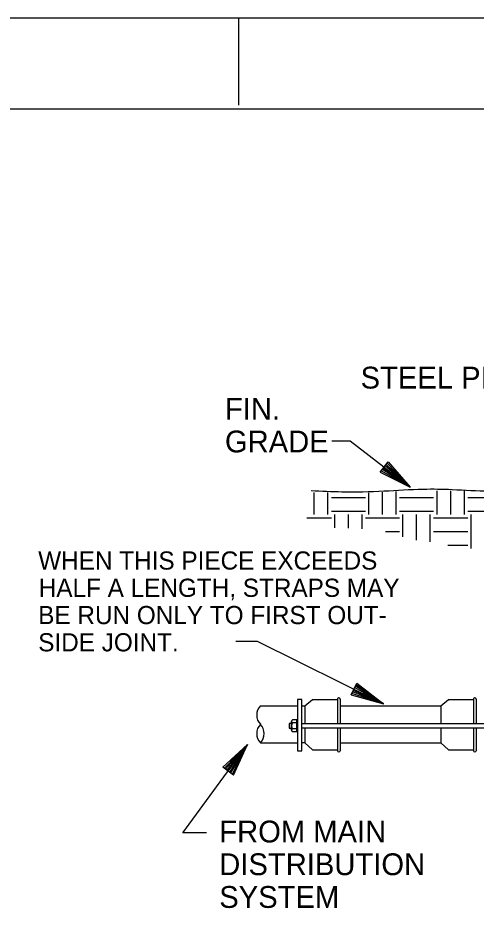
# Model space of a CAD drawing. Extents: x 9999.96 to 10005.26, y 9999.88 to 10002.38.
# Drawn here: x 10001.0957 to 10001.3058, y 10001.9764 to 10002.3845 of the extents above; entities that cross this region are included whole.
import ezdxf

# ---------------------------------------------------------------- set-up
doc = ezdxf.new("R2010")
doc.units = 0
doc.layers.add('Level 1', color=7, linetype='Continuous')
doc.layers.add('Level 2', color=7, linetype='Continuous')

msp = doc.modelspace()

# ---------------------------------------------------------------- linework, layer by layer
at = {"layer": 'Level 1'}
for p, q in [((9999.96033, 10002.38453), (10003.46033, 10002.38453)), ((10001.19683, 10002.38453), (10001.19683, 10002.3445)), ((10000.127, 10002.34286), (10003.41867, 10002.34286))]:
    msp.add_line(p, q, dxfattribs=at)
at = {"layer": 'Level 2'}
for p, q in [((10001.26183, 10002.17618), (10001.26551, 10002.18096)), ((10001.2756, 10002.1694), (10001.26322, 10002.17799)), ((10001.26364, 10002.17855), (10001.2756, 10002.1694)), ((10001.2756, 10002.1694), (10001.2641, 10002.17915)), ((10001.2756, 10002.1694), (10001.26455, 10002.17974)), ((10001.2756, 10002.1694), (10001.265, 10002.18031)), ((10001.26551, 10002.18096), (10001.2756, 10002.1694)), ((10001.26183, 10002.17618), (10001.2756, 10002.1694)), ((10001.2756, 10002.1694), (10001.2623, 10002.17679)), ((10001.2756, 10002.1694), (10001.26279, 10002.17747)), ((10001.2316, 10002.15684), (10001.2316, 10002.16698)), ((10001.23785, 10002.15684), (10001.23785, 10002.16698)), ((10001.2566, 10002.15684), (10001.2566, 10002.16681)), ((10001.26285, 10002.15684), (10001.26285, 10002.16714)), ((10001.2691, 10002.15684), (10001.2691, 10002.16745)), ((10001.28785, 10002.15684), (10001.28785, 10002.16775)), ((10001.2941, 10002.15684), (10001.2941, 10002.16777)), ((10001.30035, 10002.15684), (10001.30035, 10002.16788)), ((10001.23942, 10002.16466), (10001.25504, 10002.16466)), ((10001.27067, 10002.16466), (10001.28629, 10002.16466)), ((10001.30192, 10002.16466), (10001.31754, 10002.16466)), ((10001.23942, 10002.15841), (10001.25504, 10002.15841)), ((10001.27067, 10002.15841), (10001.28629, 10002.15841)), ((10001.30192, 10002.15841), (10001.31754, 10002.15841)), ((10001.22814, 10002.15528), (10001.23942, 10002.15528)), ((10001.24098, 10002.15072), (10001.24098, 10002.15684)), ((10001.24723, 10002.15053), (10001.24723, 10002.15684)), ((10001.25348, 10002.15033), (10001.25348, 10002.15684)), ((10001.25504, 10002.15528), (10001.27067, 10002.15528)), ((10001.27223, 10002.14657), (10001.27223, 10002.15684)), ((10001.27848, 10002.1451), (10001.27848, 10002.15684)), ((10001.28473, 10002.14425), (10001.28473, 10002.15684)), ((10001.28629, 10002.15528), (10001.30192, 10002.15528)), ((10001.30348, 10002.14122), (10001.30348, 10002.15684)), ((10001.26425, 10002.14903), (10001.27067, 10002.14903)), ((10001.28629, 10002.14903), (10001.30192, 10002.14903)), ((10001.29275, 10002.14278), (10001.30192, 10002.14278)), ((10001.24843, 10002.07413), (10001.25111, 10002.07952)), ((10001.26325, 10002.07013), (10001.24944, 10002.07617)), ((10001.24974, 10002.0768), (10001.26325, 10002.07013)), ((10001.26325, 10002.07013), (10001.25008, 10002.07747)), ((10001.26325, 10002.07013), (10001.25041, 10002.07815)), ((10001.26325, 10002.07013), (10001.25074, 10002.07878)), ((10001.25111, 10002.07952), (10001.26325, 10002.07013)), ((10001.23077, 10002.07194), (10001.22718, 10002.06903)), ((10001.24225, 10002.07194), (10001.23077, 10002.07194)), ((10001.24225, 10002.07217), (10001.24225, 10002.06098)), ((10001.24343, 10002.07217), (10001.24343, 10002.06098)), ((10001.24843, 10002.07413), (10001.26325, 10002.07013)), ((10001.26325, 10002.07013), (10001.24877, 10002.07481)), ((10001.26325, 10002.07013), (10001.24913, 10002.07557)), ((10001.2931, 10002.07194), (10001.28951, 10002.06903)), ((10001.30458, 10002.07194), (10001.2931, 10002.07194)), ((10001.30458, 10002.07217), (10001.30458, 10002.06106)), ((10001.30576, 10002.07217), (10001.30576, 10002.06106)), ((10001.22394, 10002.06903), (10001.20691, 10002.06903)), ((10001.22718, 10002.06903), (10001.22583, 10002.06903)), ((10001.22718, 10002.06903), (10001.22718, 10002.06105)), ((10001.28954, 10002.06903), (10001.24347, 10002.06903)), ((10001.28951, 10002.06903), (10001.28951, 10002.06105)), ((10001.2212, 10002.05792), (10001.2212, 10002.06202)), ((10001.22353, 10002.06134), (10001.22163, 10002.06134)), ((10001.22353, 10002.06271), (10001.22164, 10002.06271)), ((10001.22353, 10002.05723), (10001.22353, 10002.06271)), ((10001.22582, 10002.06106), (10001.39957, 10002.06106)), ((10001.22353, 10002.05859), (10001.22163, 10002.05859)), ((10001.22353, 10002.05723), (10001.22163, 10002.05723)), ((10001.39957, 10002.05897), (10001.22593, 10002.05897)), ((10001.22718, 10002.05897), (10001.22718, 10002.05216)), ((10001.24225, 10002.05905), (10001.24225, 10002.04857)), ((10001.24343, 10002.05905), (10001.24343, 10002.04857)), ((10001.28951, 10002.05897), (10001.28951, 10002.05216)), ((10001.30458, 10002.05897), (10001.30458, 10002.04857)), ((10001.30576, 10002.05897), (10001.30576, 10002.04857)), ((10001.18971, 10002.041), (10001.20103, 10002.05135)), ((10001.20103, 10002.05135), (10001.19036, 10002.04051)), ((10001.20103, 10002.05135), (10001.19094, 10002.04007)), ((10001.20103, 10002.05135), (10001.19154, 10002.03964)), ((10001.19215, 10002.03919), (10001.20103, 10002.05135)), ((10001.20103, 10002.05135), (10001.19272, 10002.03878)), ((10001.20103, 10002.05135), (10001.19325, 10002.03836)), ((10001.20103, 10002.05135), (10001.19395, 10002.03789)), ((10001.19456, 10002.03743), (10001.20103, 10002.05135)), ((10001.20691, 10002.05222), (10001.22394, 10002.05222)), ((10001.22718, 10002.05221), (10001.22583, 10002.05221)), ((10001.22718, 10002.05221), (10001.23081, 10002.04894)), ((10001.24349, 10002.05222), (10001.28954, 10002.05222)), ((10001.28951, 10002.05221), (10001.29315, 10002.04894)), ((10001.23081, 10002.04894), (10001.24225, 10002.04894)), ((10001.29315, 10002.04894), (10001.30458, 10002.04894)), ((10001.19456, 10002.03743), (10001.18971, 10002.041))]:
    msp.add_line(p, q, dxfattribs=at)
for points in [[(10001.23955, 10002.19063), (10001.24795, 10002.19063), (10001.2756, 10002.1694)], [(10001.19559, 10002.09877), (10001.20547, 10002.09877), (10001.26325, 10002.07013)], [(10001.22119, 10002.0611), (10001.22004, 10002.0611), (10001.22004, 10002.05884), (10001.22119, 10002.05884)], [(10001.18226, 10002.01086), (10001.1714, 10002.01086), (10001.20103, 10002.05135)]]:
    msp.add_lwpolyline(points, dxfattribs=at)
msp.add_lwpolyline([(10001.22394, 10002.07211), (10001.22394, 10002.04856), (10001.22582, 10002.04856), (10001.22582, 10002.07211)], close=True, dxfattribs=at)
for centre, radius, start, end in [((10001.24284, 10002.07217), 0.000589, 0, 180), ((10001.30517, 10002.07217), 0.000589, 0, 180), ((10001.21127, 10002.06488), 0.00607, 135.9788, 224.0225), ((10001.21127, 10002.05644), 0.00607, 135.9775, 224.0212), ((10001.20254, 10002.05644), 0.00607, 315.9788, 44.0225), ((10001.22198, 10002.06202), 0.000766, 116.7827, 241.8391), ((10001.22374, 10002.05997), 0.00253, 147.0062, 212.943), ((10001.22197, 10002.05791), 0.000766, 117.8877, 242.0342), ((10001.24284, 10002.04857), 0.000589, 180, 0), ((10001.30517, 10002.04857), 0.000589, 180, 0)]:
    msp.add_arc(centre, radius, start, end, dxfattribs=at)
msp.add_spline([(10001.32029, 10002.16835), (10001.31184, 10002.16767), (10001.29476, 10002.16818), (10001.28147, 10002.16835), (10001.26352, 10002.16749), (10001.2442, 10002.16715), (10001.23022, 10002.16767)], degree=3, dxfattribs=at)

# ---------------------------------------------------------------- texts
for s, height, p in [('STEEL PIPE', 0.01, (10001.2528, 10002.21458)), ('FIN. ', 0.01, (10001.19063, 10002.20032)), ('GRADE', 0.01, (10001.19063, 10002.18532)), ('WHEN THIS PIECE EXCEEDS', 0.0083333, (10001.10506, 10002.13159)), ('HALF A LENGTH, STRAPS MAY', 0.0083333, (10001.10531, 10002.11909)), ('BE RUN ONLY TO FIRST OUT-', 0.0083333, (10001.10506, 10002.10659)), ('SIDE JOINT.', 0.0083333, (10001.10506, 10002.09409)), ('FROM MAIN ', 0.01, (10001.18803, 10002.00652)), ('DISTRIBUTION', 0.01, (10001.18803, 10001.99152)), ('SYSTEM', 0.01, (10001.18803, 10001.97652))]:
    msp.add_text(s, height=height, dxfattribs=at).set_placement(p)

doc.saveas('drawing.dxf')
